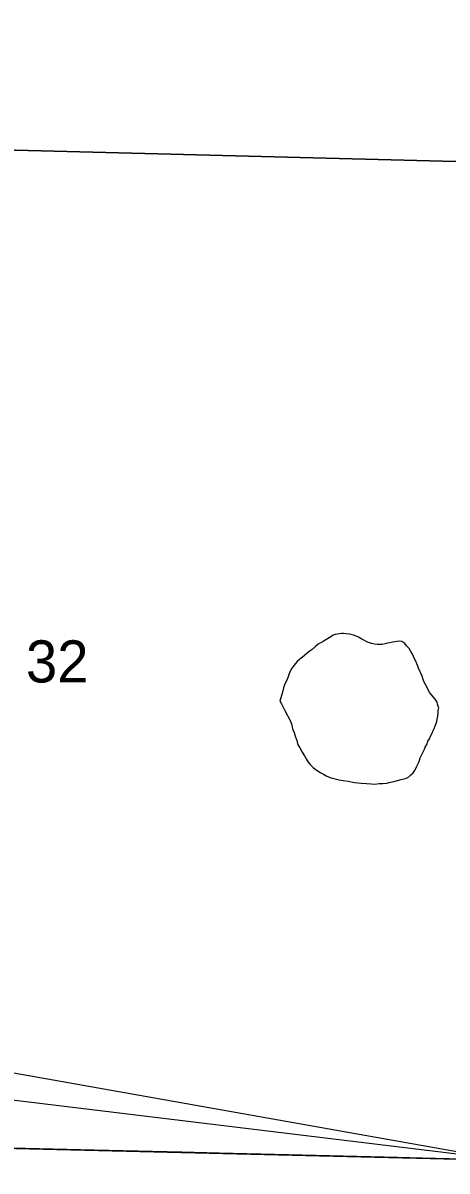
# Model space of a CAD drawing. Extents: x 0 to 68, y 0 to 52.9.
# Drawn here: x 27.525 to 27.932, y 17.855 to 18.957 of the extents above; entities that cross this region are included whole.
import ezdxf

# ---------------------------------------------------------------- set-up
doc = ezdxf.new("R2010")
doc.units = 0
for name, color, linetype in [('Default', 7, 'Continuous'), ('GM_X_Minor_Lake', 7, 'Continuous'), ('GM_X_Township', 7, 'Continuous'), ('GM_X_Township_Road', 7, 'Continuous'), ('SH_Data', 7, 'Continuous')]:
    doc.layers.add(name, color=color, linetype=linetype)

msp = doc.modelspace()

# ---------------------------------------------------------------- linework, layer by layer
at = {"layer": 'Default'}
for points in [[(27.0892, 19.8116), (28.062, 19.7892), (28.0517, 18.8207), (27.0824, 18.8456)], [(28.0517, 18.8207), (28.0387, 17.8641), (28.0216, 17.8643), (27.0669, 17.8874), (27.0824, 18.8456)], [(27.0362, 17.8879), (27.0669, 17.8874), (28.0216, 17.8643), (27.9711, 16.927), (26.9878, 16.9576)]]:
    msp.add_lwpolyline(points, close=True, dxfattribs=at)
at = {"layer": 'GM_X_Minor_Lake'}
for points in [[(27.915, 18.3138), (27.9108, 18.3217), (27.9093, 18.3247), (27.9086, 18.3265), (27.9076, 18.3298), (27.9043, 18.3376), (27.9036, 18.3394), (27.9026, 18.3416), (27.9015, 18.3442), (27.9004, 18.3464), (27.8993, 18.3487), (27.8983, 18.3509), (27.8968, 18.3535), (27.8954, 18.3564), (27.8928, 18.359), (27.891, 18.3612), (27.8881, 18.3631), (27.8855, 18.3635), (27.8833, 18.3632), (27.8815, 18.3628), (27.8793, 18.3625), (27.8767, 18.3618), (27.8745, 18.3615), (27.8723, 18.3608), (27.8693, 18.3601), (27.8664, 18.3601), (27.8645, 18.3601), (27.862, 18.3605), (27.859, 18.3613), (27.8554, 18.3624), (27.8517, 18.3643), (27.8499, 18.3654), (27.8466, 18.3673), (27.8444, 18.3681), (27.8418, 18.3692), (27.8382, 18.37), (27.8348, 18.3704), (27.8323, 18.3708), (27.8304, 18.3708), (27.8242, 18.3698), (27.8223, 18.3691), (27.8201, 18.3677), (27.8168, 18.3655), (27.8138, 18.3637), (27.8119, 18.3626), (27.8101, 18.3619), (27.8079, 18.3605), (27.8056, 18.3583), (27.8023, 18.3554), (27.8004, 18.354), (27.7974, 18.3518), (27.7948, 18.3497), (27.793, 18.3482), (27.7904, 18.346), (27.7878, 18.3439), (27.7863, 18.3421), (27.784, 18.3392), (27.7822, 18.3366), (27.781, 18.3337), (27.7799, 18.3315), (27.7791, 18.3293), (27.7776, 18.3253), (27.7761, 18.3224), (27.7749, 18.3187), (27.7739, 18.3144)], [(27.7739, 18.3144), (27.7714, 18.3058), (27.7729, 18.3033), (27.7743, 18.3), (27.7762, 18.297), (27.7816, 18.2867), (27.7827, 18.2831), (27.7835, 18.2794), (27.7849, 18.2757), (27.786, 18.2724), (27.7867, 18.2706), (27.7875, 18.268), (27.7886, 18.264), (27.7904, 18.261), (27.7926, 18.257), (27.7948, 18.2533), (27.7966, 18.2504), (27.7984, 18.2474), (27.8003, 18.2452), (27.8032, 18.2423), (27.805, 18.2405), (27.8076, 18.239), (27.8098, 18.2375), (27.8131, 18.2357), (27.8164, 18.2338), (27.8204, 18.2323), (27.8244, 18.2312), (27.8281, 18.2305), (27.8321, 18.2297), (27.8369, 18.229), (27.8427, 18.2279), (27.8493, 18.2271), (27.8545, 18.2267), (27.8589, 18.2264), (27.8622, 18.2263), (27.8666, 18.2267), (27.8699, 18.2267), (27.8739, 18.227), (27.8772, 18.2281), (27.8805, 18.2289), (27.8842, 18.2296), (27.8875, 18.2307), (27.8904, 18.2314), (27.8926, 18.2321), (27.8948, 18.2332), (27.8967, 18.235), (27.8992, 18.2372), (27.9007, 18.2394), (27.9022, 18.2427), (27.9037, 18.2453), (27.9048, 18.2478), (27.9059, 18.2515), (27.9099, 18.2599), (27.9107, 18.2618), (27.9121, 18.2643), (27.9132, 18.2676), (27.9147, 18.2698), (27.9158, 18.2724), (27.9169, 18.2746), (27.918, 18.2771), (27.9191, 18.2797), (27.9202, 18.2823), (27.921, 18.2845), (27.9217, 18.2863), (27.9221, 18.2885), (27.9228, 18.2914), (27.9232, 18.2943), (27.9232, 18.2973), (27.9236, 18.2991), (27.9232, 18.3009), (27.9225, 18.3031), (27.9221, 18.305), (27.9203, 18.3076), (27.915, 18.3138)]]:
    msp.add_lwpolyline(points, dxfattribs=at)
at = {"layer": 'GM_X_Township'}
for points in [[(28.0252, 17.8646), (27.3046, 17.882), (26.8251, 17.8904), (26.2396, 17.894), (26.2354, 17.8938), (26.1021, 17.8962), (26.1058, 18.0236), (26.1074, 18.0683), (26.1074, 18.0738), (26.1154, 18.3824), (26.121, 18.5869), (26.1254, 18.7811), (26.125, 18.8069), (26.1262, 18.8531), (26.1264, 18.9004), (26.1279, 18.961)], [(26.0998, 17.5098), (26.0998, 17.512), (26.0966, 17.5616), (26.0969, 17.5773), (26.1019, 17.8088), (26.102, 17.8285), (26.1021, 17.8962), (26.2354, 17.8938), (26.2396, 17.894), (26.8251, 17.8904), (27.3046, 17.882), (28.0252, 17.8646)]]:
    msp.add_lwpolyline(points, dxfattribs=at)
at = {"layer": 'GM_X_Township_Road'}
msp.add_lwpolyline([(27.3116, 17.8812), (27.3626, 17.88), (27.4225, 17.8788), (27.5514, 17.8762), (27.6773, 17.8733), (27.7132, 17.8723), (27.8061, 17.8701), (27.884, 17.8682), (27.956, 17.8665), (28.0159, 17.8652), (28.0237, 17.8649)], dxfattribs=at)
at = {"layer": 'SH_Data'}
msp.add_lwpolyline([(24.3814, 18.506), (27.9859, 17.8658), (24.3814, 18.3036)], close=True, dxfattribs=at)

# ---------------------------------------------------------------- texts
at = {"layer": 'Default'}
msp.add_text('32', height=0.04038, rotation=0, dxfattribs=at).set_placement((27.5278, 18.3238))

doc.saveas('drawing.dxf')
